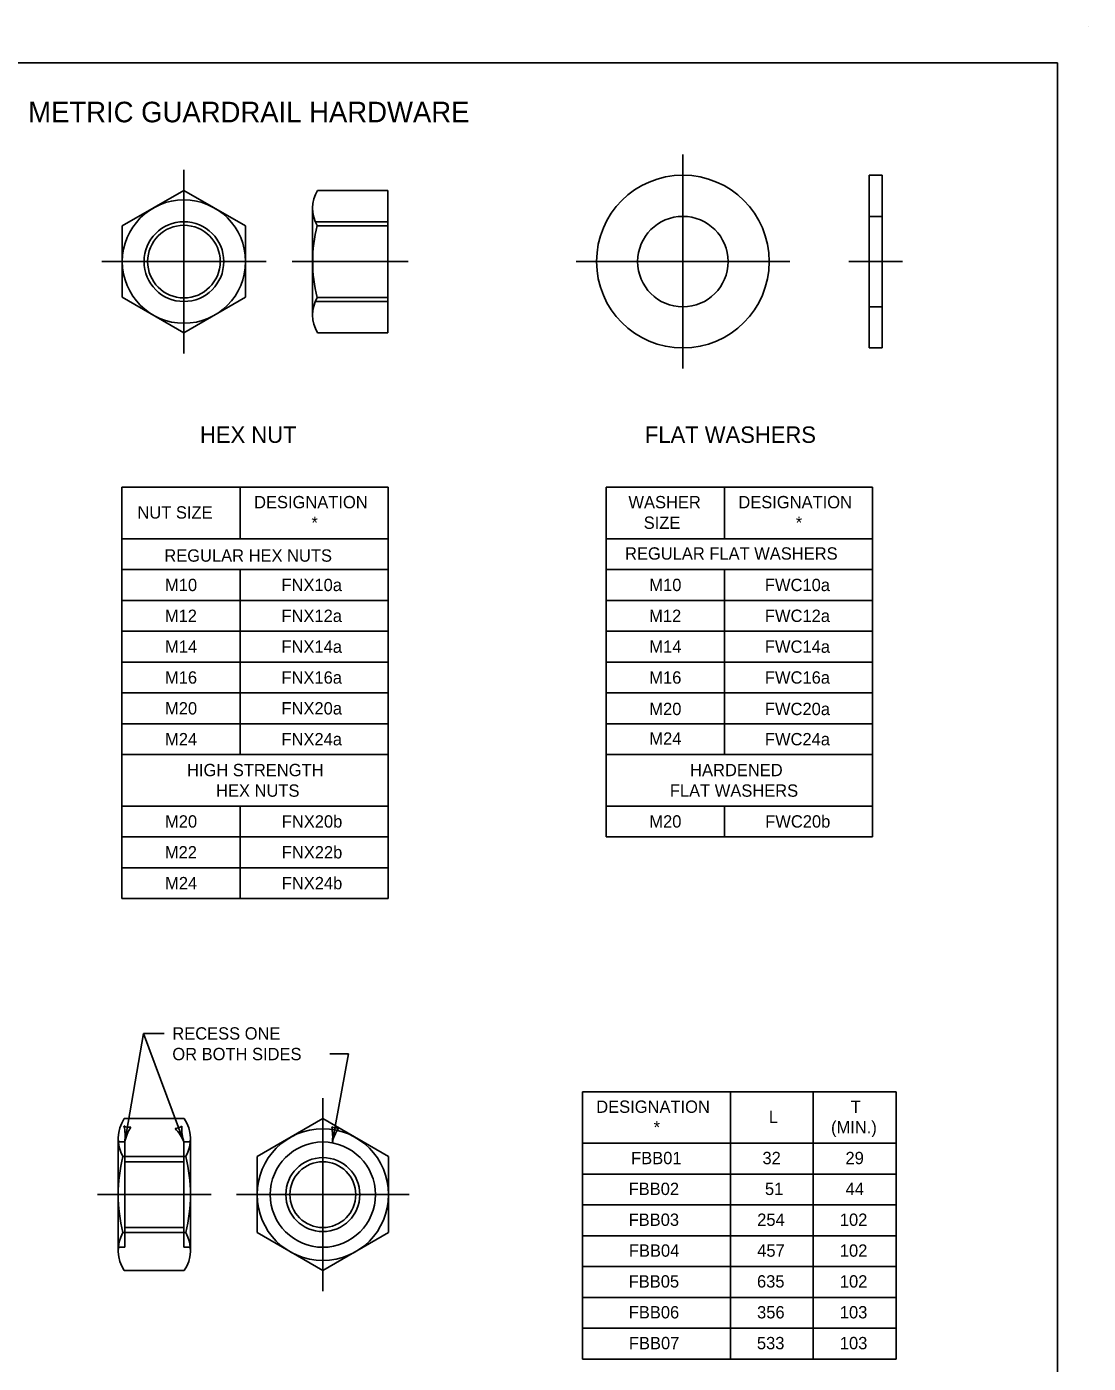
# Model space of a CAD drawing. Extents: x 49991.4 to 50021, y 49987.6 to 50011.4.
# Drawn here: x 50011.74 to 50016.9, y 49992.68 to 49999.18 of the extents above; entities that cross this region are included whole.
import ezdxf

# ---------------------------------------------------------------- set-up
doc = ezdxf.new("R2010")
doc.units = 0
for name, color, linetype in [('Level 1', 7, 'Continuous'), ('Level 2', 7, 'Continuous'), ('Level 3', 7, 'Continuous'), ('Level 4', 7, 'Continuous'), ('Level 5', 7, 'Continuous')]:
    doc.layers.add(name, color=color, linetype=linetype)

msp = doc.modelspace()

# ---------------------------------------------------------------- linework, layer by layer
at = {"layer": 'Level 1'}
for p, q in [((50016.9001, 49999.1756), (50016.9001, 49999.1756)), ((50015.8347, 49997.6135), (50015.8347, 49998.4535)), ((50015.8347, 49998.4535), (50015.8967, 49998.4535)), ((50015.8967, 49997.6135), (50015.8967, 49998.4535)), ((50012.4999, 49998.3799), (50012.1999, 49998.2067)), ((50012.7999, 49998.2067), (50012.4999, 49998.3799)), ((50013.1495, 49998.3799), (50013.4916, 49998.3799)), ((50013.4916, 49997.687), (50013.4916, 49998.3799)), ((50013.1263, 49997.7739), (50013.1263, 49998.2925)), ((50012.1999, 49997.8602), (50012.1999, 49998.2067)), ((50012.7999, 49997.8602), (50012.7999, 49998.2067)), ((50013.1487, 49998.2081), (50013.4916, 49998.2081)), ((50012.4999, 49997.687), (50012.1999, 49997.8602)), ((50012.7999, 49997.8602), (50012.4999, 49997.687)), ((50013.1487, 49997.8588), (50013.4916, 49997.8588)), ((50013.1495, 49997.687), (50013.4916, 49997.687)), ((50015.8347, 49997.6135), (50015.8967, 49997.6135)), ((50012.5019, 49993.8656), (50012.2099, 49993.8656)), ((50012.8558, 49993.6809), (50013.1758, 49993.8656)), ((50013.1758, 49993.8656), (50013.4958, 49993.6809)), ((50012.1799, 49993.768), (50012.1799, 49993.2242)), ((50012.5319, 49993.768), (50012.5319, 49993.2242)), ((50012.5084, 49993.6809), (50012.2033, 49993.6809)), ((50012.8558, 49993.3114), (50012.8558, 49993.6809)), ((50013.4958, 49993.3114), (50013.4958, 49993.6809)), ((50012.5084, 49993.3114), (50012.2033, 49993.3114)), ((50012.8558, 49993.3114), (50013.1758, 49993.1266)), ((50013.1758, 49993.1266), (50013.4958, 49993.3114)), ((50012.5019, 49993.1266), (50012.2099, 49993.1266))]:
    msp.add_line(p, q, dxfattribs=at)
msp.add_lwpolyline([(49999.3835, 49998.9992), (50016.7501, 49998.9992), (50016.7501, 49987.7988), (49999.3835, 49987.7988)], close=True, dxfattribs=at)
for centre, radius in [((50014.9276, 49998.0335), 0.42), ((50012.4999, 49998.0335), 0.3), ((50014.9276, 49998.0335), 0.22), ((50012.4999, 49998.0335), 0.1765), ((50013.1758, 49993.4961), 0.32), ((50013.1758, 49993.4961), 0.256), ((50013.1758, 49993.4961), 0.16)]:
    msp.add_circle(centre, radius, dxfattribs=at)
for centre, radius, start, end in [((50013.2995, 49998.2933), 0.1732, 150, 209.44718), ((50013.8192, 49998.0335), 0.6928, 165.39844, 194.6015), ((50013.2995, 49997.7736), 0.1732, 150.55289, 210.00006), ((50012.3536, 49993.768), 0.1737, 145.81935, 210.12922), ((50012.3582, 49993.768), 0.1737, 329.87078, 34.18065), ((50012.9189, 49993.4961), 0.739, 165.52244, 194.47742), ((50011.7929, 49993.4961), 0.739, 345.52258, 14.47756), ((50012.3536, 49993.2242), 0.1737, 149.87078, 214.18065), ((50012.3582, 49993.2242), 0.1737, 325.81935, 30.12922)]:
    msp.add_arc(centre, radius, start, end, dxfattribs=at)
at = {"layer": 'Level 2'}
for p, q in [((50012.1974, 49996.936), (50013.4941, 49996.936)), ((50012.1974, 49996.936), (50012.1974, 49994.936)), ((50012.7741, 49996.686), (50012.7741, 49996.936)), ((50012.7741, 49996.686), (50012.7741, 49996.936)), ((50013.4941, 49994.936), (50013.4941, 49996.936)), ((50014.5537, 49995.236), (50014.5537, 49996.936)), ((50014.5537, 49996.936), (50015.8503, 49996.936)), ((50015.1303, 49996.686), (50015.1303, 49996.936)), ((50015.8503, 49995.236), (50015.8503, 49996.936)), ((50012.1974, 49996.686), (50013.4941, 49996.686)), ((50012.1974, 49996.686), (50013.4941, 49996.686)), ((50014.5537, 49996.686), (50015.8503, 49996.686)), ((50012.1974, 49996.536), (50013.4941, 49996.536)), ((50012.7741, 49995.636), (50012.7741, 49996.536)), ((50014.5537, 49996.536), (50015.8503, 49996.536)), ((50015.1303, 49995.636), (50015.1303, 49996.536)), ((50012.1974, 49996.386), (50013.4941, 49996.386)), ((50014.5537, 49996.386), (50015.8503, 49996.386)), ((50012.1974, 49996.236), (50013.4941, 49996.236)), ((50014.5537, 49996.236), (50015.8503, 49996.236)), ((50012.1974, 49996.086), (50013.4941, 49996.086)), ((50014.5537, 49996.086), (50015.8503, 49996.086)), ((50012.1974, 49995.936), (50013.4941, 49995.936)), ((50014.5537, 49995.936), (50015.8503, 49995.936)), ((50012.1974, 49995.786), (50013.4941, 49995.786)), ((50014.5537, 49995.786), (50015.8503, 49995.786)), ((50012.1974, 49995.636), (50013.4941, 49995.636)), ((50014.5537, 49995.636), (50015.8503, 49995.636)), ((50012.1974, 49995.386), (50013.4941, 49995.386)), ((50012.7741, 49994.936), (50012.7741, 49995.386)), ((50014.5537, 49995.386), (50015.8503, 49995.386)), ((50015.1303, 49995.236), (50015.1303, 49995.386)), ((50012.1974, 49995.236), (50013.4941, 49995.236)), ((50014.5537, 49995.236), (50015.8503, 49995.236)), ((50012.1974, 49995.086), (50013.4941, 49995.086)), ((50012.1974, 49994.936), (50013.4941, 49994.936)), ((50014.4387, 49992.6961), (50014.4387, 49993.9961)), ((50014.4387, 49993.9961), (50015.9654, 49993.9961)), ((50015.1587, 49992.6961), (50015.1587, 49993.9961)), ((50015.562, 49992.6961), (50015.562, 49993.9961)), ((50015.9654, 49992.6961), (50015.9654, 49993.9961)), ((50014.4387, 49993.7461), (50015.9654, 49993.7461)), ((50014.4387, 49993.5961), (50015.9654, 49993.5961)), ((50014.4387, 49993.4461), (50015.9654, 49993.4461)), ((50014.4387, 49993.2961), (50015.9654, 49993.2961)), ((50014.4387, 49993.1461), (50015.9654, 49993.1461)), ((50014.4387, 49992.9961), (50015.9654, 49992.9961)), ((50014.4387, 49992.8461), (50015.9654, 49992.8461)), ((50014.4387, 49992.6961), (50015.9654, 49992.6961))]:
    msp.add_line(p, q, dxfattribs=at)
at = {"layer": 'Level 3'}
for p, q in [((50012.3035, 49994.28), (50012.2119, 49993.7521)), ((50012.4035, 49994.28), (50012.3035, 49994.28)), ((50012.3035, 49994.28), (50012.4999, 49993.7521)), ((50013.2103, 49994.18), (50013.3004, 49994.18)), ((50013.3004, 49994.18), (50013.2217, 49993.748))]:
    msp.add_line(p, q, dxfattribs=at)
for centre, radius, start, end in [((50012.2338, 49993.8784), 0.0548, 242.29742, 278.01978), ((50011.9806, 49993.7806), 0.233, 352.98591, 12.23576), ((50012.4292, 49993.7051), 0.2223, 147.61461, 167.79812), ((50012.4552, 49993.8723), 0.0548, 272.53571, 308.25807), ((50012.2858, 49993.6602), 0.233, 23.2242, 42.47405), ((50012.7113, 49993.821), 0.2223, 177.8529, 198.03641), ((50013.2447, 49993.8741), 0.0548, 241.80869, 277.53105), ((50012.9907, 49993.7784), 0.233, 352.49718, 11.74703), ((50013.4386, 49993.6991), 0.2223, 147.12588, 167.30939)]:
    msp.add_arc(centre, radius, start, end, dxfattribs=at)
at = {"layer": 'Level 4'}
for p, q in [((50013.1393, 49998.2276), (50013.4916, 49998.2276)), ((50015.8347, 49998.2535), (50015.8967, 49998.2535)), ((50013.1393, 49997.8393), (50013.4916, 49997.8393)), ((50015.8347, 49997.8135), (50015.8967, 49997.8135)), ((50012.1799, 49993.7521), (50012.2119, 49993.7521)), ((50012.2119, 49993.2401), (50012.2119, 49993.7521)), ((50012.4999, 49993.2401), (50012.4999, 49993.7521)), ((50012.5319, 49993.7521), (50012.4999, 49993.7521)), ((50012.4999, 49993.6561), (50012.2119, 49993.6561)), ((50012.4999, 49993.3361), (50012.2119, 49993.3361)), ((50012.1799, 49993.2401), (50012.2119, 49993.2401)), ((50012.5319, 49993.2401), (50012.4999, 49993.2401))]:
    msp.add_line(p, q, dxfattribs=at)
for centre, radius in [((50012.4999, 49998.0335), 0.1941), ((50013.1758, 49993.4961), 0.18)]:
    msp.add_circle(centre, radius, dxfattribs=at)
at = {"layer": 'Level 5'}
for p, q in [((50014.9276, 49997.5135), (50014.9276, 49998.5535)), ((50012.4999, 49997.587), (50012.4999, 49998.4799)), ((50012.8999, 49998.0335), (50012.0999, 49998.0335)), ((50013.0263, 49998.0335), (50013.5916, 49998.0335)), ((50015.4476, 49998.0335), (50014.4076, 49998.0335)), ((50015.7347, 49998.0335), (50015.9967, 49998.0335)), ((50013.1758, 49993.0266), (50013.1758, 49993.9656)), ((50012.6319, 49993.4961), (50012.0799, 49993.4961)), ((50012.7558, 49993.4961), (50013.5958, 49993.4961))]:
    msp.add_line(p, q, dxfattribs=at)

# ---------------------------------------------------------------- texts
at = {"layer": 'Level 2'}
for s, height, p in [('METRIC GUARDRAIL HARDWARE', 0.1, (50011.7422, 49998.7108)), ('HEX NUT', 0.08, (50012.5782, 49997.1519)), ('FLAT WASHERS', 0.08, (50014.7429, 49997.1519)), ('DESIGNATION', 0.06, (50012.8413, 49996.8337)), ('WASHER', 0.06, (50014.6627, 49996.8337)), ('DESIGNATION', 0.06, (50015.1976, 49996.8337)), ('NUT SIZE', 0.06, (50012.2738, 49996.7837)), ('*', 0.06, (50013.1206, 49996.7337)), ('SIZE', 0.06, (50014.737, 49996.7337)), ('*', 0.06, (50015.4769, 49996.7337)), ('REGULAR HEX NUTS', 0.06, (50012.4045, 49996.574)), ('REGULAR FLAT WASHERS', 0.06, (50014.6462, 49996.584)), ('M10', 0.06, (50012.4081, 49996.431)), ('FNX10a', 0.06, (50012.9746, 49996.431)), ('M10', 0.06, (50014.7644, 49996.431)), ('FWC10a', 0.06, (50015.3268, 49996.431)), ('M12', 0.06, (50012.4072, 49996.281)), ('FNX12a', 0.06, (50012.9746, 49996.281)), ('M12', 0.06, (50014.7635, 49996.281)), ('FWC12a', 0.06, (50015.3268, 49996.281)), ('M14', 0.06, (50012.4084, 49996.131)), ('FNX14a', 0.06, (50012.9746, 49996.131)), ('M14', 0.06, (50014.7647, 49996.131)), ('FWC14a', 0.06, (50015.3268, 49996.131)), ('M16', 0.06, (50012.4078, 49995.981)), ('FNX16a', 0.06, (50012.9746, 49995.981)), ('M16', 0.06, (50014.7641, 49995.981)), ('FWC16a', 0.06, (50015.3268, 49995.981)), ('M20', 0.06, (50012.4081, 49995.831)), ('FNX20a', 0.06, (50012.9746, 49995.831)), ('M20', 0.06, (50014.7644, 49995.828)), ('FWC20a', 0.06, (50015.3268, 49995.828)), ('M24', 0.06, (50012.4083, 49995.681)), ('FNX24a', 0.06, (50012.9746, 49995.681)), ('M24', 0.06, (50014.7646, 49995.684)), ('FWC24a', 0.06, (50015.3268, 49995.681)), ('HIGH STRENGTH', 0.06, (50012.515, 49995.5309)), ('HARDENED', 0.06, (50014.9629, 49995.531)), ('HEX NUTS', 0.06, (50012.6564, 49995.4309)), ('FLAT WASHERS', 0.06, (50014.8642, 49995.431)), ('M20', 0.06, (50012.4081, 49995.281)), ('FNX20b', 0.06, (50012.9762, 49995.281)), ('M20', 0.06, (50014.7644, 49995.281)), ('FWC20b', 0.06, (50015.3284, 49995.281)), ('M22', 0.06, (50012.4072, 49995.131)), ('FNX22b', 0.06, (50012.9762, 49995.131)), ('M24', 0.06, (50012.4084, 49994.981)), ('FNX24b', 0.06, (50012.9762, 49994.981)), ('RECESS ONE', 0.06, (50012.4435, 49994.25)), ('OR BOTH SIDES', 0.06, (50012.4435, 49994.1498)), ('DESIGNATION', 0.06, (50014.5061, 49993.8938)), ('T', 0.06, (50015.7443, 49993.8938)), ('L', 0.06, (50015.3458, 49993.8438)), ('*', 0.06, (50014.7854, 49993.7938)), ('(MIN.)', 0.06, (50015.6484, 49993.7938)), ('FBB01', 0.06, (50014.6759, 49993.6442)), ('32', 0.06, (50015.3149, 49993.6442)), ('29', 0.06, (50015.7189, 49993.6442)), ('FBB02', 0.06, (50014.6637, 49993.4942)), ('51', 0.06, (50015.327, 49993.4942)), ('44', 0.06, (50015.7195, 49993.4942)), ('FBB03', 0.06, (50014.6637, 49993.3442)), ('254', 0.06, (50015.2892, 49993.3442)), ('102', 0.06, (50015.6913, 49993.3442)), ('FBB04', 0.06, (50014.6649, 49993.1942)), ('457', 0.06, (50015.2893, 49993.1942)), ('102', 0.06, (50015.6913, 49993.1942)), ('FBB05', 0.06, (50014.664, 49993.0442)), ('635', 0.06, (50015.2882, 49993.0442)), ('102', 0.06, (50015.6914, 49993.0442)), ('FBB06', 0.06, (50014.6643, 49992.8942)), ('356', 0.06, (50015.2886, 49992.8942)), ('103', 0.06, (50015.6913, 49992.8942)), ('FBB07', 0.06, (50014.6651, 49992.7442)), ('533', 0.06, (50015.2879, 49992.7442)), ('103', 0.06, (50015.6913, 49992.7442))]:
    msp.add_text(s, height=height, dxfattribs=at).set_placement(p)

doc.saveas('drawing.dxf')
